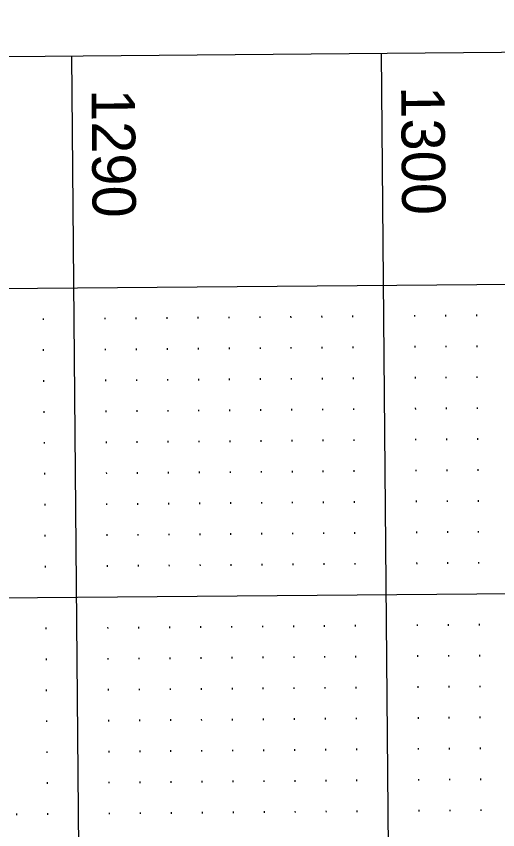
# Model space of a CAD drawing. Extents: x 2149873 to 2152007, y 140538 to 142349.
# Drawn here: x 2150266.8 to 2150344.5, y 142037.2 to 142168.7 of the extents above; entities that cross this region are included whole.
import ezdxf

# ---------------------------------------------------------------- set-up
doc = ezdxf.new("R2010")
doc.units = 0
for name, color, linetype in [('SHT_Plan_Profile_Sheet_Elev_Txt', 7, 'Continuous'), ('SHT_Profile_Grid_Major', 7, 'Continuous'), ('SHT_Profile_Grid_Minor', 7, 'Continuous'), ('SHT_Sheet_Border', 7, 'Continuous')]:
    doc.layers.add(name, color=color, linetype=linetype)

msp = doc.modelspace()

# ---------------------------------------------------------------- linework, layer by layer
at = {"layer": 'SHT_Profile_Grid_Major'}
for p, q in [((2150325.71, 142162.69), (2150339.5, 140587.76)), ((2150275.71, 142162.26), (2150289.5, 140587.32)), ((2149976.49, 142072.13), (2150476.47, 142076.51))]:
    msp.add_line(p, q, dxfattribs=at)
at = {"layer": 'SHT_Profile_Grid_Minor'}
for p, q in [((2150331.08, 142120.37), (2150331.09, 142120.12)), ((2150336.08, 142120.41), (2150336.09, 142120.16)), ((2150341.08, 142120.45), (2150341.09, 142120.2)), ((2150271.09, 142119.84), (2150271.09, 142119.59)), ((2150281.09, 142119.93), (2150281.09, 142119.68)), ((2150286.09, 142119.97), (2150286.09, 142119.72)), ((2150291.08, 142120.01), (2150291.09, 142119.76)), ((2150296.08, 142120.06), (2150296.09, 142119.81)), ((2150301.08, 142120.1), (2150301.09, 142119.85)), ((2150306.08, 142120.15), (2150306.09, 142119.9)), ((2150311.08, 142120.19), (2150311.09, 142119.94)), ((2150316.08, 142120.23), (2150316.09, 142119.98)), ((2150321.08, 142120.28), (2150321.09, 142120.03)), ((2150301.13, 142115.1), (2150301.13, 142114.85)), ((2150306.13, 142115.15), (2150306.13, 142114.9)), ((2150311.13, 142115.19), (2150311.13, 142114.94)), ((2150316.13, 142115.23), (2150316.13, 142114.98)), ((2150321.13, 142115.28), (2150321.13, 142115.03)), ((2150331.13, 142115.37), (2150331.13, 142115.12)), ((2150336.13, 142115.41), (2150336.13, 142115.16)), ((2150341.13, 142115.45), (2150341.13, 142115.2)), ((2150271.13, 142114.84), (2150271.13, 142114.59)), ((2150281.13, 142114.93), (2150281.13, 142114.68)), ((2150286.13, 142114.97), (2150286.13, 142114.72)), ((2150291.13, 142115.02), (2150291.13, 142114.77)), ((2150296.13, 142115.06), (2150296.13, 142114.81)), ((2150271.17, 142109.84), (2150271.18, 142109.59)), ((2150281.17, 142109.93), (2150281.17, 142109.68)), ((2150286.17, 142109.97), (2150286.17, 142109.72)), ((2150291.17, 142110.02), (2150291.17, 142109.77)), ((2150296.17, 142110.06), (2150296.17, 142109.81)), ((2150301.17, 142110.1), (2150301.17, 142109.85)), ((2150306.17, 142110.15), (2150306.17, 142109.9)), ((2150311.17, 142110.19), (2150311.17, 142109.94)), ((2150316.17, 142110.23), (2150316.17, 142109.98)), ((2150321.17, 142110.28), (2150321.17, 142110.03)), ((2150331.17, 142110.37), (2150331.17, 142110.12)), ((2150336.17, 142110.41), (2150336.17, 142110.16)), ((2150341.17, 142110.45), (2150341.17, 142110.2)), ((2150271.22, 142104.84), (2150271.22, 142104.59)), ((2150281.22, 142104.93), (2150281.22, 142104.68)), ((2150286.22, 142104.97), (2150286.22, 142104.72)), ((2150291.22, 142105.02), (2150291.22, 142104.77)), ((2150296.22, 142105.06), (2150296.22, 142104.81)), ((2150301.22, 142105.1), (2150301.22, 142104.85)), ((2150306.22, 142105.15), (2150306.22, 142104.9)), ((2150311.22, 142105.19), (2150311.22, 142104.94)), ((2150316.22, 142105.23), (2150316.22, 142104.98)), ((2150321.21, 142105.28), (2150321.22, 142105.03)), ((2150331.21, 142105.37), (2150331.22, 142105.12)), ((2150336.21, 142105.41), (2150336.22, 142105.16)), ((2150341.21, 142105.45), (2150341.22, 142105.2)), ((2150271.26, 142099.84), (2150271.26, 142099.59)), ((2150281.26, 142099.93), (2150281.26, 142099.68)), ((2150286.26, 142099.97), (2150286.26, 142099.72)), ((2150291.26, 142100.02), (2150291.26, 142099.77)), ((2150296.26, 142100.06), (2150296.26, 142099.81)), ((2150301.26, 142100.1), (2150301.26, 142099.85)), ((2150306.26, 142100.15), (2150306.26, 142099.9)), ((2150311.26, 142100.19), (2150311.26, 142099.94)), ((2150316.26, 142100.23), (2150316.26, 142099.98)), ((2150321.26, 142100.28), (2150321.26, 142100.03)), ((2150331.26, 142100.37), (2150331.26, 142100.12)), ((2150336.26, 142100.41), (2150336.26, 142100.16)), ((2150341.26, 142100.45), (2150341.26, 142100.2)), ((2150331.3, 142095.37), (2150331.3, 142095.12)), ((2150336.3, 142095.41), (2150336.3, 142095.16)), ((2150341.3, 142095.45), (2150341.3, 142095.2)), ((2150271.3, 142094.84), (2150271.31, 142094.59)), ((2150281.3, 142094.93), (2150281.31, 142094.68)), ((2150286.3, 142094.97), (2150286.31, 142094.72)), ((2150291.3, 142095.02), (2150291.31, 142094.77)), ((2150296.3, 142095.06), (2150296.31, 142094.81)), ((2150301.3, 142095.1), (2150301.31, 142094.85)), ((2150306.3, 142095.15), (2150306.31, 142094.9)), ((2150311.3, 142095.19), (2150311.31, 142094.94)), ((2150316.3, 142095.23), (2150316.3, 142094.98)), ((2150321.3, 142095.28), (2150321.3, 142095.03)), ((2150301.35, 142090.1), (2150301.35, 142089.85)), ((2150306.35, 142090.15), (2150306.35, 142089.9)), ((2150311.35, 142090.19), (2150311.35, 142089.94)), ((2150316.35, 142090.23), (2150316.35, 142089.98)), ((2150321.35, 142090.28), (2150321.35, 142090.03)), ((2150331.35, 142090.37), (2150331.35, 142090.12)), ((2150336.35, 142090.41), (2150336.35, 142090.16)), ((2150341.35, 142090.45), (2150341.35, 142090.2)), ((2150271.35, 142089.84), (2150271.35, 142089.59)), ((2150281.35, 142089.93), (2150281.35, 142089.68)), ((2150286.35, 142089.97), (2150286.35, 142089.72)), ((2150291.35, 142090.02), (2150291.35, 142089.77)), ((2150296.35, 142090.06), (2150296.35, 142089.81)), ((2150271.39, 142084.84), (2150271.39, 142084.59)), ((2150281.39, 142084.93), (2150281.39, 142084.68)), ((2150286.39, 142084.97), (2150286.39, 142084.72)), ((2150291.39, 142085.02), (2150291.39, 142084.77)), ((2150296.39, 142085.06), (2150296.39, 142084.81)), ((2150301.39, 142085.1), (2150301.39, 142084.85)), ((2150306.39, 142085.15), (2150306.39, 142084.9)), ((2150311.39, 142085.19), (2150311.39, 142084.94)), ((2150316.39, 142085.24), (2150316.39, 142084.99)), ((2150321.39, 142085.28), (2150321.39, 142085.03)), ((2150331.39, 142085.37), (2150331.39, 142085.12)), ((2150336.39, 142085.41), (2150336.39, 142085.16)), ((2150341.39, 142085.45), (2150341.39, 142085.2)), ((2150271.44, 142079.84), (2150271.44, 142079.59)), ((2150281.44, 142079.93), (2150281.44, 142079.68)), ((2150286.44, 142079.97), (2150286.44, 142079.72)), ((2150291.43, 142080.02), (2150291.44, 142079.77)), ((2150296.43, 142080.06), (2150296.44, 142079.81)), ((2150301.43, 142080.1), (2150301.44, 142079.85)), ((2150306.43, 142080.15), (2150306.44, 142079.9)), ((2150311.43, 142080.19), (2150311.44, 142079.94)), ((2150316.43, 142080.24), (2150316.44, 142079.99)), ((2150321.43, 142080.28), (2150321.44, 142080.03)), ((2150331.43, 142080.37), (2150331.44, 142080.12)), ((2150336.43, 142080.41), (2150336.44, 142080.16)), ((2150341.43, 142080.45), (2150341.44, 142080.2)), ((2150336.52, 142070.41), (2150336.52, 142070.16)), ((2150341.52, 142070.45), (2150341.52, 142070.2)), ((2150271.52, 142069.84), (2150271.53, 142069.59)), ((2150281.52, 142069.93), (2150281.53, 142069.68)), ((2150286.52, 142069.97), (2150286.52, 142069.72)), ((2150291.52, 142070.02), (2150291.52, 142069.77)), ((2150296.52, 142070.06), (2150296.52, 142069.81)), ((2150301.52, 142070.1), (2150301.52, 142069.85)), ((2150306.52, 142070.15), (2150306.52, 142069.9)), ((2150311.52, 142070.19), (2150311.52, 142069.94)), ((2150316.52, 142070.24), (2150316.52, 142069.99)), ((2150321.52, 142070.28), (2150321.52, 142070.03)), ((2150331.52, 142070.37), (2150331.52, 142070.12)), ((2150306.57, 142065.15), (2150306.57, 142064.9)), ((2150311.57, 142065.19), (2150311.57, 142064.94)), ((2150316.57, 142065.24), (2150316.57, 142064.99)), ((2150321.57, 142065.28), (2150321.57, 142065.03)), ((2150331.56, 142065.37), (2150331.57, 142065.12)), ((2150336.56, 142065.41), (2150336.57, 142065.16)), ((2150341.56, 142065.45), (2150341.57, 142065.2)), ((2150271.57, 142064.84), (2150271.57, 142064.59)), ((2150281.57, 142064.93), (2150281.57, 142064.68)), ((2150286.57, 142064.97), (2150286.57, 142064.72)), ((2150291.57, 142065.02), (2150291.57, 142064.77)), ((2150296.57, 142065.06), (2150296.57, 142064.81)), ((2150301.57, 142065.1), (2150301.57, 142064.85)), ((2150281.61, 142059.93), (2150281.61, 142059.68)), ((2150286.61, 142059.97), (2150286.61, 142059.72)), ((2150291.61, 142060.02), (2150291.61, 142059.77)), ((2150296.61, 142060.06), (2150296.61, 142059.81)), ((2150301.61, 142060.1), (2150301.61, 142059.85)), ((2150306.61, 142060.15), (2150306.61, 142059.9)), ((2150311.61, 142060.19), (2150311.61, 142059.94)), ((2150316.61, 142060.24), (2150316.61, 142059.99)), ((2150321.61, 142060.28), (2150321.61, 142060.03)), ((2150331.61, 142060.37), (2150331.61, 142060.12)), ((2150336.61, 142060.41), (2150336.61, 142060.16)), ((2150341.61, 142060.45), (2150341.61, 142060.2)), ((2150271.61, 142059.84), (2150271.61, 142059.59)), ((2150271.65, 142054.84), (2150271.66, 142054.59)), ((2150281.65, 142054.93), (2150281.66, 142054.68)), ((2150286.65, 142054.97), (2150286.66, 142054.72)), ((2150291.65, 142055.02), (2150291.66, 142054.77)), ((2150296.65, 142055.06), (2150296.66, 142054.81)), ((2150301.65, 142055.1), (2150301.66, 142054.85)), ((2150306.65, 142055.15), (2150306.66, 142054.9)), ((2150311.65, 142055.19), (2150311.66, 142054.94)), ((2150316.65, 142055.24), (2150316.65, 142054.99)), ((2150321.65, 142055.28), (2150321.65, 142055.03)), ((2150331.65, 142055.37), (2150331.65, 142055.12)), ((2150336.65, 142055.41), (2150336.65, 142055.16)), ((2150341.65, 142055.46), (2150341.65, 142055.21)), ((2150271.7, 142049.84), (2150271.7, 142049.59)), ((2150281.7, 142049.93), (2150281.7, 142049.68)), ((2150286.7, 142049.97), (2150286.7, 142049.72)), ((2150291.7, 142050.02), (2150291.7, 142049.77)), ((2150296.7, 142050.06), (2150296.7, 142049.81)), ((2150301.7, 142050.11), (2150301.7, 142049.86)), ((2150306.7, 142050.15), (2150306.7, 142049.9)), ((2150311.7, 142050.19), (2150311.7, 142049.94)), ((2150316.7, 142050.24), (2150316.7, 142049.99)), ((2150321.7, 142050.28), (2150321.7, 142050.03)), ((2150331.7, 142050.37), (2150331.7, 142050.12)), ((2150336.7, 142050.41), (2150336.7, 142050.16)), ((2150341.7, 142050.46), (2150341.7, 142050.21)), ((2150336.74, 142045.41), (2150336.74, 142045.16)), ((2150341.74, 142045.46), (2150341.74, 142045.21)), ((2150271.74, 142044.84), (2150271.74, 142044.59)), ((2150281.74, 142044.93), (2150281.74, 142044.68)), ((2150286.74, 142044.97), (2150286.74, 142044.72)), ((2150291.74, 142045.02), (2150291.74, 142044.77)), ((2150296.74, 142045.06), (2150296.74, 142044.81)), ((2150301.74, 142045.11), (2150301.74, 142044.86)), ((2150306.74, 142045.15), (2150306.74, 142044.9)), ((2150311.74, 142045.19), (2150311.74, 142044.94)), ((2150316.74, 142045.24), (2150316.74, 142044.99)), ((2150321.74, 142045.28), (2150321.74, 142045.03)), ((2150331.74, 142045.37), (2150331.74, 142045.12)), ((2150306.78, 142040.15), (2150306.79, 142039.9)), ((2150311.78, 142040.19), (2150311.79, 142039.94)), ((2150316.78, 142040.24), (2150316.79, 142039.99)), ((2150321.78, 142040.28), (2150321.79, 142040.03)), ((2150331.78, 142040.37), (2150331.79, 142040.12)), ((2150336.78, 142040.41), (2150336.79, 142040.16)), ((2150341.78, 142040.46), (2150341.79, 142040.21)), ((2150266.79, 142039.8), (2150266.79, 142039.55)), ((2150271.79, 142039.84), (2150271.79, 142039.59)), ((2150281.79, 142039.93), (2150281.79, 142039.68)), ((2150286.79, 142039.97), (2150286.79, 142039.72)), ((2150291.79, 142040.02), (2150291.79, 142039.77)), ((2150296.78, 142040.06), (2150296.79, 142039.81)), ((2150301.78, 142040.11), (2150301.79, 142039.86))]:
    msp.add_line(p, q, dxfattribs=at)
at = {"layer": 'SHT_Sheet_Border'}
msp.add_line((2149976.05, 142122.13), (2150476.04, 142126.51), dxfattribs=at)
msp.add_lwpolyline([(2151008.19, 142168.67), (2151021.97, 140593.73), (2149972.01, 140584.54), (2149958.23, 142159.48)], close=True, dxfattribs=at)

# ---------------------------------------------------------------- texts
at = {"layer": 'SHT_Plan_Profile_Sheet_Elev_Txt'}
for s, p in [('1290', (2150278.92, 142156.89)), ('1300', (2150328.92, 142157.33))]:
    msp.add_text(s, height=7, rotation=270.5015, dxfattribs=at).set_placement(p)

doc.saveas('drawing.dxf')
